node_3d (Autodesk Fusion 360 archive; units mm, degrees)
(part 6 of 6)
sketch "Sketch17" plane through (0, 0, -5) normal (0, 0, -1) x axis (1, 0, 0)
  curve K1 (44.3163, 11.4617) -> (45.4617, 10.3162)
  line L1 (23.6838, 11.4617) -> (44.3163, 11.4617)
  curve K2 (22.5383, 10.3163) -> (23.6838, 11.4617)
  line L2 (22.5383, -10.3162) -> (22.5383, 10.3163)
  curve K3 (23.6837, -11.4617) -> (22.5383, -10.3162)
  line L3 (44.3162, -11.4617) -> (23.6837, -11.4617)
  curve K4 (45.4617, -10.3163) -> (44.3162, -11.4617)
  line L4 (45.4617, 10.3162) -> (45.4617, -10.3163)
  line L5 (34.0169, -2.7499) -> (34.0169, 2.7499)
  line L6 (36.75, 0) -> (31.25, 0)
  line L7 (36.75, -1) -> (31.25, -1)
  line L8 (36.75, 1) -> (31.25, 1)
  line L9 (30.4383, 1) -> (31.4383, 1)
  line L10 (31.4383, -1) -> (30.4383, -1)
  line L11 (36.5617, -1) -> (37.5955, -1)
  line L12 (37.5955, 1) -> (36.5617, 1)
  line L13 (33.0169, -2.7499) -> (33.0169, 2.7499)
  line L14 (35.0169, -2.7499) -> (35.0169, 2.7499)
  line L15 (33.0169, 3.5683) -> (33.0169, 2.5683)
  line L16 (35.0169, 2.5551) -> (35.0169, 3.5683)
  line L17 (35.0169, -2.5551) -> (35.0169, -3.5683)
  line L18 (33.0169, -3.5683) -> (33.0169, -2.5683)
  line L19 (31.502, -1.15) -> (30.4383, -1.15)
  line L20 (30.4383, 1.15) -> (31.502, 1.15)
  line L21 (32.8669, 3.5683) -> (32.8669, 2.5683)
  line L22 (35.1669, 2.5551) -> (35.1669, 3.5683)
  line L23 (37.5955, 1.15) -> (36.5617, 1.15)
  line L24 (36.5617, -1.15) -> (37.5955, -1.15)
  line L25 (32.8669, -3.5683) -> (32.8669, -2.5683)
  line L26 (35.1669, -2.5551) -> (35.1669, -3.5683)
  circle C1 centre (34, 0) radius 2.75
  arc A1 centre (30.4383, 0) radius 1 clockwise from (29.4383, 0) to (30.4383, 1)
  arc A2 centre (30.4383, 0) radius 1 clockwise from (30.4383, -1) to (29.4383, 0)
  arc A3 centre (37.5955, 0) radius 1 clockwise from (38.5955, 0) to (37.5955, -1)
  arc A4 centre (37.5955, 0) radius 1 clockwise from (37.5955, 1) to (38.5955, 0)
  arc A5 centre (34.0169, 3.5683) radius 1 clockwise from (33.0169, 3.5683) to (34.0169, 4.5683)
  arc A6 centre (34.0169, 3.5683) radius 1 clockwise from (34.0169, 4.5683) to (35.0169, 3.5683)
  arc A7 centre (34.0169, -3.5683) radius 1 clockwise from (35.0169, -3.5683) to (34.0169, -4.5683)
  arc A8 centre (34.0169, -3.5683) radius 1 clockwise from (34.0169, -4.5683) to (33.0169, -3.5683)
  arc A9 centre (30.4383, 0) radius 1.15 clockwise from (30.4383, -1.15) to (29.2883, 0)
  arc A10 centre (30.4383, 0) radius 1.15 clockwise from (29.2883, 0) to (30.4383, 1.15)
  circle C2 centre (34, 0) radius 2.9
  arc A11 centre (34.0169, 3.5683) radius 1.15 clockwise from (32.8669, 3.5683) to (34.0169, 4.7183)
  arc A12 centre (34.0169, 3.5683) radius 1.15 clockwise from (34.0169, 4.7183) to (35.1669, 3.5683)
  arc A13 centre (37.5955, 0) radius 1.15 clockwise from (37.5955, 1.15) to (38.7455, 0)
  arc A14 centre (37.5955, 0) radius 1.15 clockwise from (38.7455, 0) to (37.5955, -1.15)
  arc A15 centre (34.0169, -3.5683) radius 1.15 clockwise from (34.0169, -4.7183) to (32.8669, -3.5683)
  arc A16 centre (34.0169, -3.5683) radius 1.15 clockwise from (35.1669, -3.5683) to (34.0169, -4.7183)
  point P11 (34.0169, 2.7499)
  point P12 (34.0169, -2.7499)
  point P13 (31.25, 0)
  point P14 (36.75, 0)
  point P19 (31.4383, 1)
  point P21 (31.4383, -1)
  point P15 (31.25, -1)
  point P20 (29.4383, 1)
  point P23 (29.4383, 0)
  point P26 (29.4383, 0)
  point P22 (30.4383, 1)
  point P32 (37.5955, 1)
  point P33 (38.5955, 0)
  point P25 (30.4383, -1)
  point P30 (37.5955, -1)
  point P29 (38.5955, 0)
  point P34 (36.5617, -1)
  point P35 (36.5617, 1)
  point P40 (33.0169, 2.5683)
  point P43 (35.0169, 2.5551)
  point P41 (33.0169, 4.5683)
  point P42 (35.0169, 4.5683)
  point P44 (34.0169, 4.5683)
  point P47 (34.0169, 4.5683)
  point P57 (33.0169, -2.5683)
  point P53 (35.0169, -2.5551)
  point P55 (34.0169, -4.5683)
  point P45 (33.0169, 3.5683)
  point P56 (33.0169, -3.5683)
  point P52 (34.0169, -4.5683)
  point P48 (35.0169, 3.5683)
  point P51 (35.0169, -3.5683)
  point P64 (31.502, 1.15)
  point P65 (31.502, -1.15)
  coincident C1 P11
  coincident C1 P12
  vertical L5
  coincident C1 P13
  coincident C1 P14
  perpendicular L5 L6
  coincident C1 P19
  coincident L8 P19
  perpendicular L5 L9
  coincident C1 P21
  coincident P15 L10
  coincident P20 L9
  tangent L9 A1
  tangent L10 A2
  equal A1 A2
  coincident P23 P26
  symmetric L5 P22 P32
  symmetric L5 P23 P33
  symmetric L5 A1 A4
  symmetric L5 P25 P30
  symmetric L5 P26 P29
  symmetric L5 A2 A3
  coincident C1 P34
  coincident C1 P35
  coincident L13 P40
  coincident C1 P40
  parallel L13 L15
  coincident L14 P43
  coincident C1 P43
  coincident P41 L15
  tangent L15 A5
  coincident P42 L16
  tangent L16 A6
  coincident P44 P47
  symmetric L6 P40 P57
  symmetric L6 P43 P53
  symmetric L6 P44 P55
  symmetric L6 P45 P56
  symmetric L6 A5 A8
  symmetric L6 P47 P52
  symmetric L6 P48 P51
  symmetric L6 A6 A7
  concentric A1 A10
  tangent L20 A10
  coincident C1 P64
  concentric A2 A9
  tangent A9 L19
  coincident C1 P65
  dimension "d166" = 1
  dimension "d171" = -1
  dimension "d176" distance P19 P20 = 2
  dimension "d201" radius A1 = 1
  dimension "d202" = 1
  dimension "d203" = -1
  dimension "d204" distance P40 P41 = 2
  dimension "d205" distance P41 P42 = 2
  dimension "d214" radius A5 = 1
  dimension "d215" radius A6 = 1
  dimension "d261" = 0.15
  dimension "d262" = -0.15
  dimension "d263" = 0.15
  dimension "d264" = -0.15
  dimension "d265" = 0.15
  dimension "d266" = 0.15
  dimension "d267" = 0.15
offset_faces "OffsetFaces11" distance 1
offset_faces "OffsetFaces12" distance 0.3
extrude "Extrude26" cut sketch "Sketch17" profile of C1 L9 L10 A1 A2 A3 L11 A4 L12 L15 L16 A5 A6 A7 L17 A8 L18 A9 L19 A10 L20 C2 A11 L21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 to an object
sketch "Sketch18" plane through (0, 0, 0) normal (0, 0, 1) x axis (1, 0, 0)
  line L1 (18, 13.8287) -> (20.1713, 16)
  line L2 (47.8287, 16) -> (20.1713, 16)
  line L3 (18, 13.8287) -> (18, -13.8287)
  line L4 (47.8287, 16) -> (50, 13.8287)
  line L5 (50, -13.8287) -> (50, 13.8287)
  line L6 (50, -13.8287) -> (47.8287, -16)
  line L7 (20.1713, -16) -> (47.8287, -16)
  line L8 (20.1713, -16) -> (18, -13.8287)
  line L9 (50, 16) -> (18, 16)
  line L10 (50, -16) -> (50, 16)
  line L11 (18, -16) -> (50, -16)
  line L12 (18, 16) -> (18, -16)
  horizontal L9
  vertical L10
  horizontal L11
  vertical L12
extrude "Extrude27" new body sketch "Sketch18" along normal blind 12 taper -25
copy_paste_bodies "CopyPasteBodies2"
move "Move3"
offset_faces "OffsetFaces13" distance 20
copy_paste_bodies "CopyPasteBodies4"
component_from_bodies "Body->Comp3"
copy_paste_bodies "CopyPasteBodies5"
component_from_bodies "Body->Comp4"
move "Move4"
sphere_primitive "SpherePrimitive3" Diameter 60
move "Move5"
chamfer "Chamfer5" distance 2
combine "Combine10"
fillet "Fillet6" radius 1.25
shell "Shell3" innerThickness 2
sketch "Sketch26" plane through (0, 0, 0) normal (0, 0, -1) x axis (1, 0, 0)
  line L1 (46.6474, 13.7932) -> (21.3526, 13.7932)
  line L2 (47.7932, 12.6474) -> (46.6474, 13.7932)
  line L3 (47.7932, -12.6474) -> (47.7932, 12.6474)
  line L4 (46.6474, -13.7932) -> (47.7932, -12.6474)
  line L5 (21.3526, -13.7932) -> (46.6474, -13.7932)
  line L6 (20.2068, -12.6474) -> (21.3526, -13.7932)
  line L7 (20.2068, 12.6474) -> (20.2068, -12.6474)
  line L8 (21.3526, 13.7932) -> (20.2068, 12.6474)
  line L9 (47.8287, 16) -> (50, 13.8287)
  line L10 (20.1713, 16) -> (47.8287, 16)
  line L11 (18, 13.8287) -> (20.1713, 16)
  line L12 (18, -13.8287) -> (18, 13.8287)
  line L13 (20.1713, -16) -> (18, -13.8287)
  line L14 (47.8287, -16) -> (20.1713, -16)
  line L15 (50, -13.8287) -> (47.8287, -16)
  line L16 (50, 13.8287) -> (50, -13.8287)
extrude "Extrude30" new body sketch "Sketch26" profile of L1 L2 L3 L4 L5 L6 L7 L8 against normal blind 7.5 taper -25
offset_faces "OffsetFaces15" distance -6
extrude "Extrude31" cut sketch "Sketch26" against normal blind 6
combine "Combine11"
extrude "Extrude32" sketch "Sketch17" profile of C1 L9 L10 A1 A2 A3 L11 A4 L12 L15 L16 A5 A6 A7 L17 A8 L18 A9 L19 A10 L20 C2 A11 L21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 blind -1.2
combine "Combine7"
copy_paste_bodies "CopyPasteBodies3"
component_from_bodies "Body->Comp2"
shell "Shell2" innerThickness 2.17
chamfer "Chamfer4" distance 2
fillet "Fillet3" radius 5
sketch "Sketch19" plane through (0, 0, 0) normal (0, 0, 1) x axis (1, 0, 0)
  line L1 (47.8287, 16) -> (20.1713, 16)
  line L2 (50, -13.8287) -> (50, 13.8287)
  line L3 (20.1713, -16) -> (47.8287, -16)
  line L4 (18, 13.8287) -> (18, -13.8287)
  line L5 (46.6474, -13.7932) -> (21.3526, -13.7932)
  line L6 (47.7932, -12.6474) -> (46.6474, -13.7932)
  line L7 (47.7932, 12.6474) -> (47.7932, -12.6474)
  line L8 (46.6474, 13.7932) -> (47.7932, 12.6474)
  line L9 (21.3526, 13.7932) -> (46.6474, 13.7932)
  line L10 (20.2068, 12.6474) -> (21.3526, 13.7932)
  line L11 (20.2068, -12.6474) -> (20.2068, 12.6474)
  line L12 (21.3526, -13.7932) -> (20.2068, -12.6474)
  line L13 (47.8287, -16) -> (50, -13.8287)
  line L14 (18, -13.8287) -> (20.1713, -16)
  line L15 (20.1713, 16) -> (18, 13.8287)
  line L16 (50, 13.8287) -> (47.8287, 16)
extrude "Extrude28" new body sketch "Sketch19" along normal blind 6.5 taper -25
offset_faces "OffsetFaces14" distance -5.5
combine "Combine8"
combine "Combine9"
extrude "Extrude29" sketch "Sketch17" profile of C1 L9 L10 A1 A2 A3 L11 A4 L12 L15 L16 A5 A6 A7 L17 A8 L18 A9 L19 A10 L20 C2 A11 L21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 blind -1.8
move_face "MoveFace4"
move_face "MoveFace3"
fillet "Fillet2" radius 3
extrude "Extrude19" cut sketch "Sketch17" profile of C1 L9 L10 against normal blind 1.8
extrude "Extrude20" sketch "Sketch9" to an object
extrude "Extrude21" sketch "Sketch17" profile of C1 L9 L10 A1 A2 C2 blind 2
extrude "Extrude22" cut sketch "Sketch9" profile of L1 L2 L3 L4 L5 L6 L7 L8 L9 L10 L11 L12 against normal blind 14
combine "Combine3"
extrude "Extrude23" new body sketch "Sketch17" profile of C1 A3 L11 A4 L12 L15 L16 A5 A6 to an object
combine "Combine4"
combine "Combine5"
offset_faces "OffsetFaces9" distance 0.1
offset_faces "OffsetFaces10" distance -0.1
extrude "Extrude24" add of existing geometry blind 1.3
extrude "Extrude25" cut sketch "Sketch17" profile of C1 L9 L10 A1 A2 A3 L11 A4 L12 L15 L16 A5 A6 A7 L17 A8 L18 A9 L19 A10 L20 C2 A11 L21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 to an object
offset_faces "OffsetFaces4" distance 2
sketch "Sketch16" plane through (0, 0, -12) normal (0, 0, -1) x axis (1, 0, 0)
  line L1 (20.42, -14.7259) -> (47.58, -14.7259)
  line L2 (19.2741, -13.58) -> (20.42, -14.7259)
  line L3 (19.2741, 13.58) -> (19.2741, -13.58)
  line L4 (20.42, 14.7259) -> (19.2741, 13.58)
  line L5 (47.58, 14.7259) -> (20.42, 14.7259)
  line L6 (48.7259, 13.58) -> (47.58, 14.7259)
  line L7 (48.7259, -13.58) -> (48.7259, 13.58)
  line L8 (47.58, -14.7259) -> (48.7259, -13.58)
  line L9 (19.2387, -16.9326) -> (17.0674, -14.7613)
  line L10 (48.7613, -16.9326) -> (19.2387, -16.9326)
  line L11 (50.9326, -14.7613) -> (48.7613, -16.9326)
  line L12 (50.9326, 14.7613) -> (50.9326, -14.7613)
  line L13 (48.7613, 16.9326) -> (50.9326, 14.7613)
  line L14 (19.2387, 16.9326) -> (48.7613, 16.9326)
  line L15 (17.0674, 14.7613) -> (19.2387, 16.9326)
  line L16 (17.0674, -14.7613) -> (17.0674, 14.7613)
  line L17 (68, -30) -> (0, -30)
  line L18 (68, 30) -> (68, -30)
  line L19 (0, 30) -> (68, 30)
  line L20 (0, -30) -> (0, 30)
  line L21 (68, 30) -> (0, -30)
  line L22 (0, 30) -> (68, -30)
  point P22 (34, 0)
  horizontal L17
  perpendicular L17 L18
  parallel L17 L19
  parallel L18 L20
  coincident L21 P22
  coincident L22 P22
extrude "Extrude15" cut sketch "Sketch16" profile of L1 L2 L3 L4 L5 L6 L7 L8 L9 L10 L11 L12 L13 L14 L15 L16 L17 L18 L19 L20 along normal blind 1
sketch "Sketch14" plane through (0, 0, -10) normal (0, 0, -1) x axis (1, 0, 0)
  line L1 (21.3526, -13.7932) -> (46.6474, -13.7932)
  line L2 (20.2068, -12.6474) -> (21.3526, -13.7932)
  line L3 (20.2068, 12.6474) -> (20.2068, -12.6474)
  line L4 (21.3526, 13.7932) -> (20.2068, 12.6474)
  line L5 (46.6474, 13.7932) -> (21.3526, 13.7932)
  line L6 (47.7932, 12.6474) -> (46.6474, 13.7932)
  line L7 (47.7932, -12.6474) -> (47.7932, 12.6474)
  line L8 (46.6474, -13.7932) -> (47.7932, -12.6474)
  line L9 (20.1713, -16) -> (18, -13.8287)
  line L10 (47.8287, -16) -> (20.1713, -16)
  line L11 (50, -13.8287) -> (47.8287, -16)
  line L12 (50, 13.8287) -> (50, -13.8287)
  line L13 (47.8287, 16) -> (50, 13.8287)
  line L14 (20.1713, 16) -> (47.8287, 16)
  line L15 (18, 13.8287) -> (20.1713, 16)
  line L16 (18, -13.8287) -> (18, 13.8287)
  curve K1 (23.7946, -7.0232) -> (26.9768, -10.2054)
  curve K2 (41.0232, -10.2054) -> (44.2054, -7.0232)
  curve K3 (44.2054, 7.0232) -> (41.0232, 10.2054)
  curve K4 (26.9768, 10.2054) -> (23.7946, 7.0232)
  line L17 (44.6844, -10.6844) -> (23.3984, 10.6016)
  line L18 (23.4131, -10.6159) -> (44.5869, 10.6159)
  line L19 (23.097, 10.903) -> (44.6844, -10.6844)
  line L20 (44.8878, 10.9177) -> (23.1122, -10.9177)
  line L21 (23.3156, -10.6844) -> (44.6844, -10.6844)
  line L22 (23.3156, 10.6844) -> (23.3156, -10.6844)
  line L23 (44.6844, 10.6844) -> (23.3156, 10.6844)
  line L24 (44.6844, -10.6844) -> (44.6844, 10.6844)
  line L25 (23.3156, 10.6844) -> (44.6844, -10.6844)
  line L26 (44.6844, 10.6844) -> (23.3156, -10.6844)
  closed curve K5 centre (43.7365, 0)
  closed curve K6 centre (52.771, 0)
  closed curve K7 centre (34, 18.771)
  closed curve K8 centre (34, 9.7365)
  closed curve K9 centre (34, 18.771)
  closed curve K10 centre (15.229, 0)
  closed curve K11 centre (24.2635, 0)
  closed curve K12 centre (15.229, 0)
  closed curve K13 centre (34, -18.771)
  closed curve K14 centre (34, -9.7365)
  closed curve K15 centre (34, -18.771)
  closed curve K16 centre (52.771, 0)
  circle C1 centre (34, 0) radius 2.75
  point P47 (34, 0)
  point P42 (34, 0)
  point P51 (34, 0)
  point P55 (34, 0)
  coincident L17 P47
  coincident L18 P47
  coincident P42 P47
  coincident L19 P51
  coincident L20 P51
  coincident P47 P51
  horizontal L21
  perpendicular L21 L22
  parallel L21 L23
  parallel L22 L24
  coincident L25 P55
  coincident L26 P55
  coincident P42 P55
  tangent K8 L21
  tangent K11 L24
extrude "Extrude13" new body sketch "Sketch14" profile of K5 K6 K1 K7 K8 K9 K2 K10 K11 K12 K3 K13 K14 K15 K4 K16 C1 L21 L22 L23 L24 against normal blind 7
offset_faces "OffsetFaces2" distance -6
sphere_primitive "SpherePrimitive1" Diameter 600
move "Move1" TranslateX 0 TranslateY 0 TranslateZ 274.9
move "Move2" TranslateX 0 TranslateY 0 TranslateZ -0.07
move_face "MoveFace1" TranslateX 0 TranslateY 0 TranslateZ 25.015
combine "Combine2"
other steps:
derived_base_feature "Derived Base Feature1"
derived_base_feature "Derived Base Feature1"
derived_base_feature "Derived Base Feature1"
base_feature "Base Feature1" bodies "shell (1)"
base_feature "Base Feature1" bodies "shell (2)"
derived_base_feature "Derived Base Feature1"
derived_base_feature "Derived Base Feature1"
derived_base_feature "Derived Base Feature1"
derived_base_feature "Derived Base Feature1"
derived_base_feature "Derived Base Feature1"
derived_base_feature "Derived Base Feature1"
derived_base_feature "Derived Base Feature1"
derived_base_feature "Derived Base Feature1"
derived_base_feature "Derived Base Feature1"
derived_base_feature "Derived Base Feature1"
derived_base_feature "Derived Base Feature1"
derived_base_feature "Derived Base Feature1"
derived_base_feature "Derived Base Feature1"
derived_base_feature "Derived Base Feature1"
derived_base_feature "Derived Base Feature1"
base_feature "Base Feature1"
base_feature "Base Feature1"
base_feature "Base Feature1"
base_feature "Base Feature1"
base_feature "Base Feature2" bodies "spher", "spher (1)"
base_feature "Base Feature4" bodies "shell (1)"
base_feature "Base Feature5" bodies "shell (2)"
create_component "CreateComponent1"
create_component "CreateComponent2"
create_component "CreateComponent3"
create_component "CreateComponent4"
create_component "CreateComponent5"
create_component "CreateComponent6"
create_component "CreateComponent7"
create_component "CreateComponent8"
create_component "CreateComponent9"
create_component "CreateComponent10"
create_component "CreateComponent11"
create_component "CreateComponent12"
create_component "CreateComponent13"
create_component "CreateComponent14"
create_component "CreateComponent15"
create_component "CreateComponent16"
create_component "CreateComponent17"
create_component "CreateComponent18"
create_component "CreateComponent19"
remove_body "RemoveBody1"
create_component "CreateComponent20"
remove_body "RemoveBody2"
create_component "CreateComponent22"
base_feature "Base Feature1"
remove_body "RemoveBody4"
create_component "CreateComponent23"
base_feature "Base Feature1"
remove_body "RemoveBody5"
joint_origin "JointOrigin4"
joint_origin "JointOrigin6"
joint_origin "JointOrigin1"
joint_origin "JointOrigin7"
create_component "CreateComponent1"
remove_body "RemoveBody2"
create_component "CreateComponent2"
remove_body "RemoveBody3"
base_feature "Base Feature3" bodies "shell", "shell (1)"
create_component "CreateComponent3"
base_feature "Base Feature1" bodies "shell (1)"
remove_body "RemoveBody4"
create_component "CreateComponent4"
remove_body "RemoveBody5"
create_component "CreateComponent5"
remove_body "RemoveBody6"
named bodies: "spher", "shell", "spher (1)", "shell (1)", "shell (2)"

design "pogo_connect_with_wire"
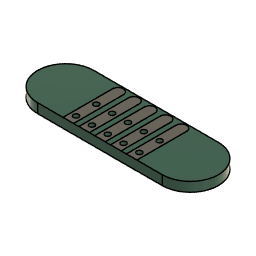
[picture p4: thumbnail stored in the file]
description: KiCad electronic assembly
part number: pogo_connect_with_wire 1
description: Part Number
part number: pogo_with_connector_mockup_PCB
base_feature "Base Feature"
sketch "Sketch1" plane through (0, -138.75, 0) normal (0, -1, 0) x axis (1, 0, 0)
  line L1 (184, 1.51) -> (184, 0)
  line L2 (164, 1.51) -> (184, 1.51)
  line L3 (164, 0) -> (164, 1.51)
  line L4 (184, 0) -> (164, 0)
sketch "Sketch2" plane through (0, 0, 0) normal (0, 0, -1) x axis (1, 0, 0)
  line L1 (164, 138.75) -> (184, 138.75)
  line L2 (184, 129.75) -> (164, 129.75)
  line L3 (168.0738, 138.75) -> (169.7662, 138.75)
  line L4 (168.07, 130.77) -> (168.07, 138.67)
  line L5 (169.77, 138.67) -> (169.77, 130.77)
  line L6 (170.6138, 138.75) -> (172.3062, 138.75)
  line L7 (170.61, 130.77) -> (170.61, 138.67)
  line L8 (172.31, 138.67) -> (172.31, 130.77)
  line L9 (173.1538, 138.75) -> (174.8462, 138.75)
  line L10 (173.15, 130.77) -> (173.15, 138.67)
  line L11 (174.85, 138.67) -> (174.85, 130.77)
  line L12 (175.6938, 138.75) -> (177.3862, 138.75)
  line L13 (175.69, 130.77) -> (175.69, 138.67)
  line L14 (177.39, 138.67) -> (177.39, 130.77)
  line L15 (178.2338, 138.75) -> (179.9262, 138.75)
  line L16 (178.23, 130.77) -> (178.23, 138.67)
  line L17 (179.93, 138.67) -> (179.93, 130.77)
  arc A1 centre (184, 134.25) radius 4.5 clockwise from (184, 138.75) to (184, 129.75)
  arc A2 centre (164, 134.25) radius 4.5 clockwise from (164, 129.75) to (164, 138.75)
  circle C1 centre (168.92, 137.5) radius 0.425
  circle C2 centre (171.46, 137.5) radius 0.425
  circle C3 centre (174, 137.5) radius 0.425
  circle C4 centre (176.54, 137.5) radius 0.425
  circle C5 centre (179.08, 137.5) radius 0.425
  circle C6 centre (168.92, 134.25) radius 0.425
  circle C7 centre (171.46, 134.25) radius 0.425
  circle C8 centre (174, 134.25) radius 0.425
  circle C9 centre (176.54, 134.25) radius 0.425
  circle C10 centre (179.08, 134.25) radius 0.425
  circle C11 centre (168.92, 137.5) radius 0.4
  circle C12 centre (168.92, 134.25) radius 0.4
  arc A3 centre (168.92, 138.67) radius 0.85 clockwise from (168.07, 138.67) to (168.0738, 138.75)
  arc A4 centre (168.92, 130.77) radius 0.85 clockwise from (169.77, 130.77) to (168.07, 130.77)
  arc A5 centre (168.92, 138.67) radius 0.85 clockwise from (169.7662, 138.75) to (169.77, 138.67)
  arc A6 centre (171.46, 138.67) radius 0.85 clockwise from (170.61, 138.67) to (170.6138, 138.75)
  arc A7 centre (171.46, 130.77) radius 0.85 clockwise from (172.31, 130.77) to (170.61, 130.77)
  arc A8 centre (171.46, 138.67) radius 0.85 clockwise from (172.3062, 138.75) to (172.31, 138.67)
  circle C13 centre (171.46, 134.25) radius 0.4
  circle C14 centre (171.46, 137.5) radius 0.4
  circle C15 centre (174, 137.5) radius 0.4
  circle C16 centre (174, 134.25) radius 0.4
  arc A9 centre (174, 138.67) radius 0.85 clockwise from (173.15, 138.67) to (173.1538, 138.75)
  arc A10 centre (174, 130.77) radius 0.85 clockwise from (174.85, 130.77) to (173.15, 130.77)
  arc A11 centre (174, 138.67) radius 0.85 clockwise from (174.8462, 138.75) to (174.85, 138.67)
  circle C17 centre (176.54, 137.5) radius 0.4
  circle C18 centre (176.54, 134.25) radius 0.4
  arc A12 centre (176.54, 138.67) radius 0.85 clockwise from (175.69, 138.67) to (175.6938, 138.75)
  arc A13 centre (176.54, 130.77) radius 0.85 clockwise from (177.39, 130.77) to (175.69, 130.77)
  arc A14 centre (176.54, 138.67) radius 0.85 clockwise from (177.3862, 138.75) to (177.39, 138.67)
  circle C19 centre (179.08, 137.5) radius 0.4
  circle C20 centre (179.08, 134.25) radius 0.4
  arc A15 centre (179.08, 138.67) radius 0.85 clockwise from (178.23, 138.67) to (178.2338, 138.75)
  arc A16 centre (179.08, 130.77) radius 0.85 clockwise from (179.93, 130.77) to (178.23, 130.77)
  arc A17 centre (179.08, 138.67) radius 0.85 clockwise from (179.9262, 138.75) to (179.93, 138.67)
extrude "Extrude1" add sketch "Sketch2" profile of L1 C1 C2 C3 C4 C5 C6 C7 C8 C9 C10 L3 A3 L4 A4 L5 A5 L6 A6 L7 A7 L8 A8 L9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 against normal blind 1.52 and along normal blind 0.01
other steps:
create_component "CreateComponent3"

design "pogo_bottomconnect pcb2_"
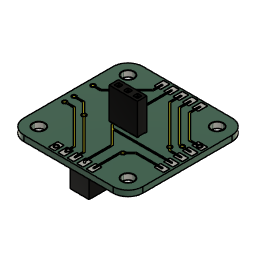
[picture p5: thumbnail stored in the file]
description: KiCad electronic assembly
part number: pogo_bottompcb2 1
description: Part Number
part number: pogo_copper
part number: pogo_pad
part number: pogo_via
part number: pogo_PCB
part number: PinSocket_2x03_P2.54mm_Vertical_SMD
part number: PinSocket_1x03_P2.54mm_Vertical
base_feature "Base Feature1"
base_feature "Base Feature1"
base_feature "Base Feature1"
base_feature "Base Feature1"
base_feature "Base Feature1"
base_feature "Base Feature1"
copy_paste "CutPaste1"
copy_paste "CutPaste2"
copy_paste "CutPaste3"
copy_paste "CutPaste4"
copy_paste "CutPaste5"
as_built_joint "As-built1"
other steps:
create_component "CreateComponent1"
create_component "CreateComponent2"
create_component "CreateComponent3"
create_component "CreateComponent4"
create_component "CreateComponent5"
create_component "CreateComponent6"
remove_instance "RemoveInstance1"
remove_instance "RemoveInstance2"
remove_instance "RemoveInstance3"
remove_instance "RemoveInstance4"
remove_instance "RemoveInstance5"

design "PCB_forkeypad1_redo"
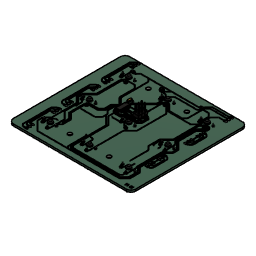
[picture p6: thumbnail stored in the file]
description: KiCad electronic assembly
part number: PCB_forkeypad1_redo 1
description: Part Number
part number: PCB_forkeypad1_redo 1.1.1
part number: PCB_forkeypad1_redo 1.1.2
part number: Header_SMD_01x03_P2.54mm_Horizontal_Male
part number: PinHeader_2x03_P2.54mm_Vertical_SMD
part number: Body
part number: Contact
part number: ContactClone
part number: Capacitor-1206
part number: D_SOD-123
base_feature "Base Feature1"
base_feature "Base Feature1"
base_feature "Base Feature1"
base_feature "Base Feature1"
base_feature "Base Feature1"
base_feature "Base Feature1"
base_feature "Base Feature1"
base_feature "Base Feature1"
base_feature "Base Feature1"
base_feature "Base Feature1"
base_feature "Base Feature1"
base_feature "Base Feature1"
base_feature "Base Feature1"
base_feature "Base Feature1"
remove_instance "RemoveInstance1"
as_built_joint "As-built1"
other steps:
create_component "CreateComponent1"
create_component "CreateComponent1"
create_component "CreateComponent2"
create_component "CreateComponent2"
create_component "CreateComponent3"
create_component "CreateComponent1"
create_component "CreateComponent2"
create_component "CreateComponent3"
create_component "CreateComponent4"
create_component "CreateComponent5"
create_component "CreateComponent1"
create_component "CreateComponent1"
create_component "CreateComponent2"
create_component "CreateComponent3"
create_component "CreateComponent6"
create_component "CreateComponent7"
create_component "CreateComponent8"
create_component "CreateComponent9"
